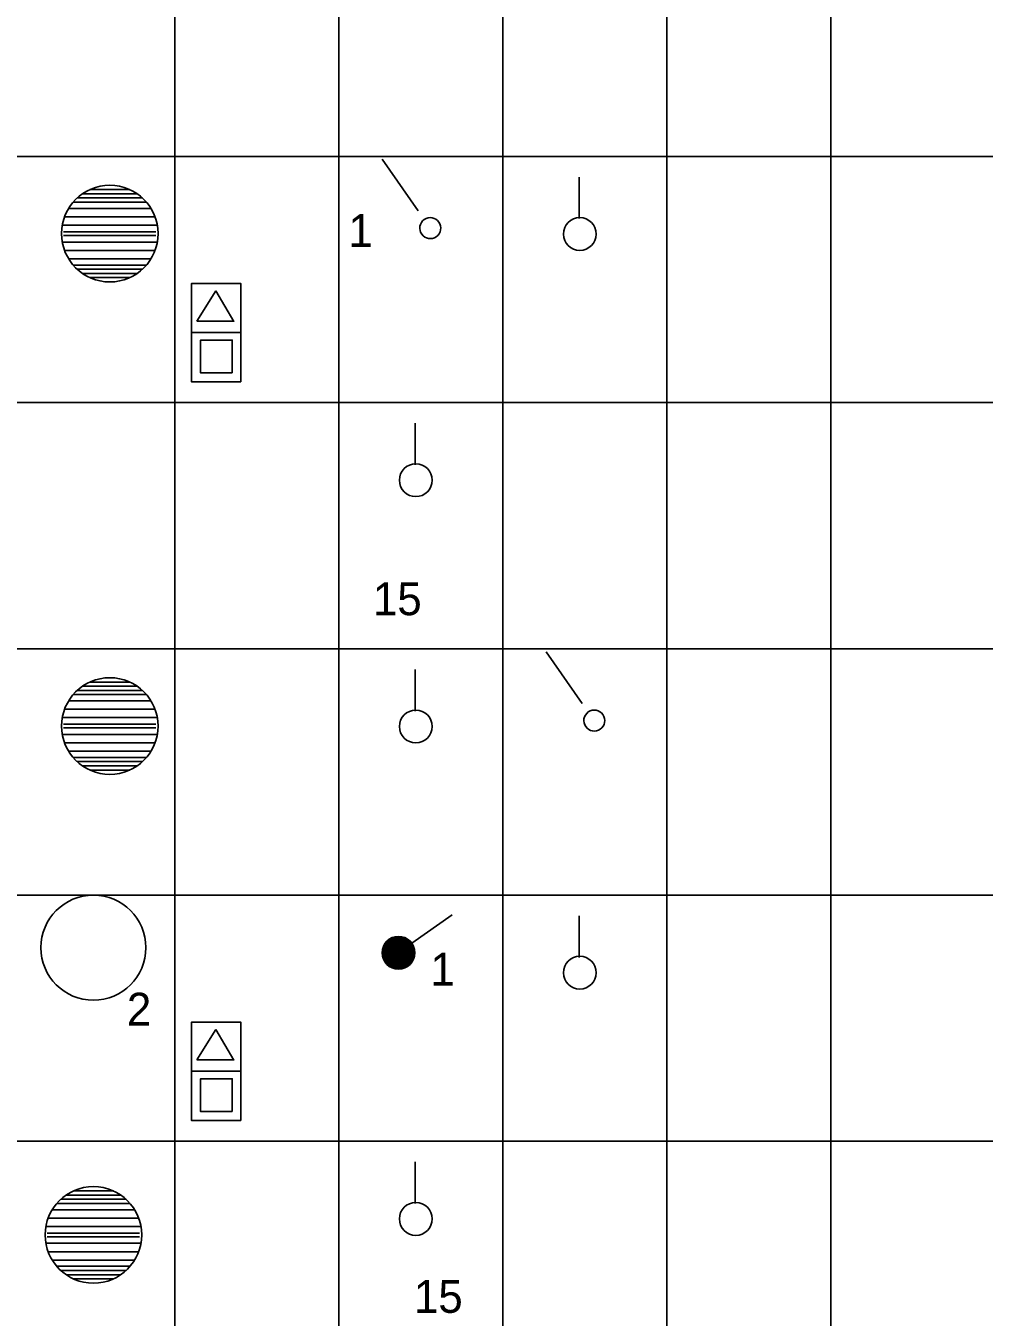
# Model space of a CAD drawing. Extents: x -28 to 822, y 61 to 665.
# Drawn here: x 134 to 192.5, y 221 to 299.7 of the extents above; entities that cross this region are included whole.
import ezdxf

# ---------------------------------------------------------------- set-up
doc = ezdxf.new("R2010")
doc.units = 0
doc.layers.add('KOLEJIŠTĚ', color=7, linetype='Continuous')

# ---------------------------------------------------------------- blocks, each defined once
blk = doc.blocks.new('HR6')
for p, q in [((-1.304, 1.895), (1.304, 1.895)), ((-0.95, 2.095), (0.95, 2.095)), ((-1.748, 1.495), (1.748, 1.495)), ((-1.555, 1.695), (1.555, 1.695)), ((-2.156, 0.8), (2.156, 0.8)), ((-1.962, 1.2), (1.962, 1.2)), ((-2.265, 0.4), (2.265, 0.4)), ((-2.2, 0.09), (2.2, 0.09)), ((-2.265, -0.4), (2.265, -0.4)), ((-2.2, -0.09), (2.2, -0.09)), ((-2.156, -0.8), (2.156, -0.8)), ((-1.962, -1.2), (1.962, -1.2)), ((-1.748, -1.495), (1.748, -1.495)), ((-1.555, -1.695), (1.555, -1.695)), ((-1.304, -1.895), (1.304, -1.895)), ((-0.95, -2.095), (0.95, -2.095))]:
    blk.add_line(p, q)
for start, end in [(0, 180), (180, 0)]:
    blk.add_arc((0, 0), 2.3, start, end)
blk = doc.blocks.new('ZT75')
at = {"xscale": 0.8, "yscale": 0.8000000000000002}
blk.add_blockref('HR6', (0, 0), dxfattribs=at)
blk = doc.blocks.new('_X10')
for p, q in [((370.452, 480.16), (371.464, 481.172)), ((370.452, 480.177), (371.447, 481.172)), ((370.452, 480.195), (371.429, 481.172)), ((370.453, 480.142), (371.482, 481.172)), ((370.453, 480.125), (371.499, 481.171)), ((370.453, 480.214), (371.411, 481.171)), ((370.454, 480.109), (371.515, 481.17)), ((370.454, 480.232), (371.392, 481.17)), ((370.455, 480.092), (371.532, 481.169)), ((370.455, 480.251), (371.373, 481.169)), ((370.457, 480.076), (371.548, 481.167)), ((370.457, 480.271), (371.353, 481.167)), ((370.458, 480.06), (371.564, 481.166)), ((370.459, 480.291), (371.334, 481.165)), ((370.46, 480.044), (371.58, 481.164)), ((370.462, 480.029), (371.596, 481.162)), ((370.462, 480.311), (371.313, 481.162)), ((370.465, 480.013), (371.611, 481.159)), ((370.465, 480.332), (371.293, 481.159)), ((370.467, 479.998), (371.626, 481.157)), ((370.469, 480.353), (371.271, 481.156)), ((370.47, 479.983), (371.641, 481.154)), ((370.473, 479.969), (371.656, 481.151)), ((370.473, 480.375), (371.249, 481.151)), ((370.476, 479.954), (371.67, 481.148)), ((370.478, 480.398), (371.227, 481.146)), ((370.479, 479.94), (371.685, 481.145)), ((370.483, 479.925), (371.699, 481.141)), ((370.484, 480.421), (371.203, 481.141)), ((370.487, 479.911), (371.713, 481.137)), ((370.49, 480.445), (371.179, 481.134)), ((370.491, 479.898), (371.727, 481.134)), ((370.495, 479.884), (371.74, 481.13)), ((370.498, 480.47), (371.154, 481.126)), ((370.499, 479.87), (371.754, 481.125)), ((370.503, 479.857), (371.767, 481.121)), ((370.506, 480.497), (371.127, 481.118)), ((370.507, 479.844), (371.78, 481.117)), ((370.512, 479.831), (371.793, 481.112)), ((370.516, 480.524), (371.1, 481.108)), ((370.517, 479.818), (371.806, 481.107)), ((370.522, 479.805), (371.819, 481.102)), ((370.527, 479.793), (371.832, 481.097)), ((370.528, 480.554), (371.071, 481.096)), ((370.532, 479.78), (371.844, 481.092)), ((370.537, 479.768), (371.856, 481.087)), ((370.541, 480.585), (371.039, 481.083)), ((370.543, 479.756), (371.869, 481.081)), ((370.549, 479.744), (371.881, 481.076)), ((370.554, 479.732), (371.893, 481.07)), ((370.557, 480.618), (371.006, 481.067)), ((370.56, 479.72), (371.904, 481.064)), ((370.566, 479.708), (371.916, 481.058)), ((370.572, 479.697), (371.928, 481.052)), ((370.577, 480.656), (370.968, 481.047)), ((370.579, 479.685), (371.939, 481.046)), ((370.585, 479.674), (371.95, 481.039)), ((370.592, 479.663), (371.961, 481.033)), ((370.598, 479.652), (371.972, 481.026)), ((370.602, 480.698), (370.926, 481.022)), ((370.605, 479.641), (371.983, 481.019)), ((370.612, 479.63), (371.994, 481.012)), ((370.619, 479.619), (372.005, 481.005)), ((370.626, 479.609), (372.015, 480.998)), ((370.633, 479.598), (372.026, 480.991)), ((370.637, 480.751), (370.873, 480.988)), ((370.64, 479.588), (372.036, 480.984)), ((370.648, 479.578), (372.046, 480.976)), ((370.655, 479.568), (372.057, 480.969)), ((370.663, 479.558), (372.067, 480.961)), ((370.671, 479.548), (372.076, 480.953)), ((370.679, 479.538), (372.086, 480.945)), ((370.687, 479.528), (372.096, 480.937)), ((370.695, 479.519), (372.105, 480.929)), ((370.703, 479.509), (372.115, 480.921)), ((370.706, 480.838), (370.786, 480.918)), ((370.712, 479.5), (372.124, 480.913)), ((370.72, 479.491), (372.133, 480.904)), ((370.729, 479.482), (372.142, 480.896)), ((370.737, 479.473), (372.151, 480.887)), ((370.746, 479.464), (372.16, 480.878)), ((370.755, 479.455), (372.169, 480.869)), ((370.764, 479.446), (372.178, 480.86)), ((370.773, 479.438), (372.186, 480.851)), ((370.782, 479.429), (372.195, 480.842)), ((370.792, 479.421), (372.203, 480.832)), ((370.801, 479.413), (372.211, 480.823)), ((370.811, 479.405), (372.219, 480.813)), ((370.821, 479.397), (372.227, 480.804)), ((370.83, 479.389), (372.235, 480.794)), ((370.84, 479.381), (372.243, 480.784)), ((370.85, 479.373), (372.251, 480.774)), ((370.86, 479.366), (372.258, 480.764)), ((370.871, 479.358), (372.266, 480.754)), ((370.881, 479.351), (372.273, 480.743)), ((370.891, 479.344), (372.28, 480.733)), ((370.902, 479.337), (372.287, 480.722)), ((370.913, 479.33), (372.294, 480.711)), ((370.924, 479.323), (372.301, 480.701)), ((370.935, 479.316), (372.308, 480.69)), ((370.946, 479.31), (372.314, 480.678)), ((370.957, 479.303), (372.321, 480.667)), ((370.968, 479.297), (372.327, 480.656)), ((370.98, 479.291), (372.333, 480.645)), ((370.991, 479.285), (372.34, 480.633)), ((371.003, 479.279), (372.346, 480.621)), ((371.015, 479.273), (372.351, 480.609)), ((371.027, 479.267), (372.357, 480.597)), ((371.039, 479.261), (372.363, 480.585)), ((371.051, 479.256), (372.368, 480.573)), ((371.063, 479.251), (372.373, 480.561)), ((371.076, 479.246), (372.379, 480.548)), ((371.089, 479.24), (372.384, 480.536)), ((371.101, 479.236), (372.389, 480.523)), ((371.114, 479.231), (372.393, 480.51)), ((371.127, 479.226), (372.398, 480.497)), ((371.141, 479.222), (372.402, 480.484)), ((371.154, 479.218), (372.407, 480.47)), ((371.167, 479.213), (372.411, 480.457)), ((371.181, 479.209), (372.415, 480.443)), ((371.195, 479.206), (372.419, 480.429)), ((371.209, 479.202), (372.422, 480.415)), ((371.223, 479.199), (372.426, 480.401)), ((371.238, 479.195), (372.429, 480.386)), ((371.252, 479.192), (372.432, 480.372)), ((371.267, 479.189), (372.435, 480.357)), ((371.282, 479.187), (372.438, 480.342)), ((371.297, 479.184), (372.44, 480.327)), ((371.313, 479.182), (372.442, 480.311)), ((371.328, 479.18), (372.444, 480.296)), ((371.344, 479.178), (372.446, 480.28)), ((371.36, 479.176), (372.448, 480.264)), ((371.376, 479.175), (372.449, 480.248)), ((371.393, 479.174), (372.45, 480.231)), ((371.41, 479.173), (372.451, 480.214)), ((371.427, 479.172), (372.452, 480.197)), ((371.444, 479.172), (372.452, 480.18)), ((371.462, 479.172), (372.452, 480.162)), ((371.48, 479.172), (372.452, 480.144)), ((371.498, 479.173), (372.451, 480.126)), ((371.517, 479.174), (372.45, 480.107)), ((371.536, 479.176), (372.449, 480.088)), ((371.556, 479.177), (372.447, 480.068)), ((371.576, 479.18), (372.444, 480.048)), ((371.596, 479.182), (372.442, 480.028)), ((371.617, 479.186), (372.438, 480.007)), ((371.639, 479.19), (372.435, 479.985)), ((371.661, 479.194), (372.43, 479.963)), ((371.684, 479.199), (372.425, 479.941)), ((371.707, 479.205), (372.419, 479.917)), ((371.732, 479.212), (372.412, 479.892)), ((371.757, 479.22), (372.404, 479.867)), ((371.784, 479.229), (372.395, 479.84)), ((371.812, 479.239), (372.385, 479.812)), ((371.841, 479.251), (372.373, 479.783)), ((371.873, 479.265), (372.359, 479.751)), ((371.908, 479.282), (372.342, 479.716)), ((371.946, 479.303), (372.322, 479.678)), ((371.991, 479.329), (372.295, 479.634)), ((372.047, 479.369), (372.256, 479.577))]:
    blk.add_line(p, q)

msp = doc.modelspace()

# ---------------------------------------------------------------- linework, layer by layer
for p, q in [((143.116, 381.738), (143.116, 141.738)), ((153.116, 381.738), (153.116, 111.738)), ((163.116, 381.738), (163.116, 111.738)), ((173.116, 381.738), (173.116, 111.738)), ((183.116, 381.738), (183.116, 111.738)), ((143.116, 366.738), (143.116, 111.738)), ((5.068, 291.738), (540.616, 291.738)), ((155.758, 291.558), (157.96, 288.412)), ((167.778, 287.941), (167.778, 290.474)), ((144.461, 281.699), (145.623, 283.552)), ((146.728, 281.672), (145.623, 283.552)), ((146.743, 281.699), (144.461, 281.699)), ((5.068, 276.738), (292.72, 276.738)), ((157.778, 272.941), (157.778, 275.474)), ((5.068, 261.738), (540.616, 261.738)), ((165.758, 261.558), (167.96, 258.412)), ((157.778, 257.941), (157.778, 260.474)), ((5.068, 246.738), (540.616, 246.738)), ((5.068, 246.738), (540.616, 246.738)), ((157.57, 243.796), (160.019, 245.529)), ((167.778, 242.941), (167.778, 245.474)), ((144.461, 236.699), (145.623, 238.552)), ((146.728, 236.672), (145.623, 238.552)), ((146.743, 236.699), (144.461, 236.699)), ((5.068, 231.738), (292.72, 231.738)), ((157.778, 227.941), (157.778, 230.474))]:
    msp.add_line(p, q)
for points in [[(147.139, 281), (144.139, 281), (144.139, 284), (147.139, 284)], [(147.139, 278), (144.139, 278), (144.139, 281), (147.139, 281)], [(146.618, 278.541), (144.691, 278.541), (144.691, 280.544), (146.618, 280.544)], [(147.139, 236), (144.139, 236), (144.139, 239), (147.139, 239)], [(147.139, 233), (144.139, 233), (144.139, 236), (147.139, 236)], [(146.618, 233.541), (144.691, 233.541), (144.691, 235.544), (146.618, 235.544)]]:
    msp.add_lwpolyline(points, close=True)
for centre, radius in [((167.81, 287.005), 1), ((157.81, 272.005), 1), ((157.81, 257.005), 1), ((138.157, 243.531), 3.2), ((156.754, 243.218), 1), ((167.81, 242.005), 1), ((157.81, 227.005), 1)]:
    msp.add_circle(centre, radius)
for centre, start, end in [((158.694, 287.363), 35, 215), ((158.694, 287.363), 215, 35), ((168.694, 257.363), 35, 215), ((168.694, 257.363), 215, 35)]:
    msp.add_arc(centre, 0.64, start, end)

# ---------------------------------------------------------------- block references
at = {"rotation": -92.29148628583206}
msp.add_blockref('_X10', (-308.183, 633.572), dxfattribs=at)
at = {"layer": 'KOLEJIŠTĚ', "xscale": 1.600000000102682, "yscale": 1.600000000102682}
for p in [(139.157, 287.031), (139.157, 257.031), (138.157, 226.031)]:
    msp.add_blockref('ZT75', p, dxfattribs=at)

# ---------------------------------------------------------------- texts
for s, p in [('1', (153.705, 286.219)), ('15', (155.198, 263.784)), ('1', (158.705, 241.219)), ('2', (140.198, 238.784)), ('15', (157.698, 221.284))]:
    msp.add_text(s, height=2).set_placement(p)

doc.saveas('drawing.dxf')
